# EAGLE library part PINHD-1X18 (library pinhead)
PIN HEADER
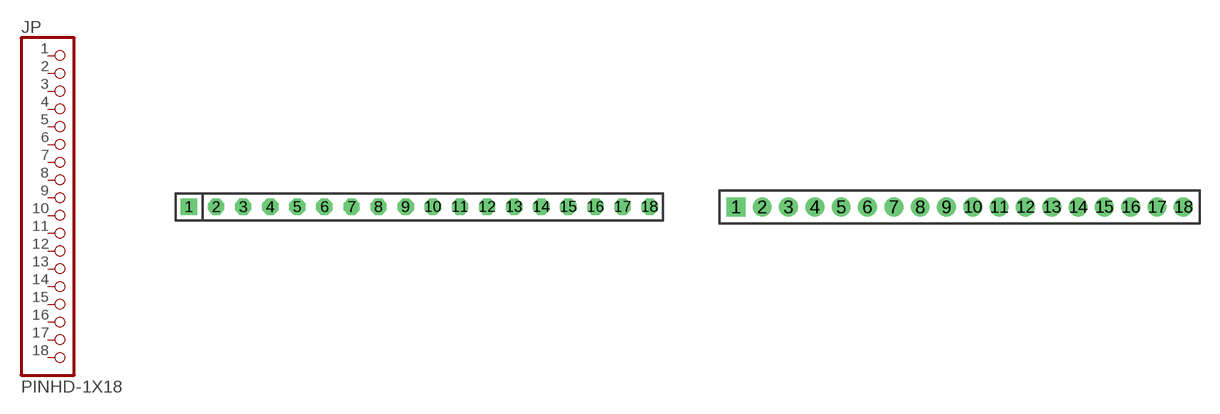
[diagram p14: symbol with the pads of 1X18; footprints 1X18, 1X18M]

Designator prefix JP

## PINHD-1X18  [1X18]
1  1  pas
2  2  pas
3  3  pas
4  4  pas
5  5  pas
6  6  pas
7  7  pas
8  8  pas
9  9  pas
10  10  pas
11  11  pas
12  12  pas
13  13  pas
14  14  pas
15  15  pas
16  16  pas
17  17  pas
18  18  pas

## PINHD-1X18M  [1X18M]
Pads as for 1X18

## Footprint 1X18 (pad centres in mm)
PIN HEADER - 0.1"
drill 1.016 square: 1 -21.59,0
drill 1.016 octagon: 2 -19.05,0; 3 -16.51,0; 4 -13.97,0; 5 -11.43,0; 6 -8.89,0; 7 -6.35,0; 8 -3.81,0; 9 -1.27,0; 10 1.27,0; 11 3.81,0; 12 6.35,0; 13 8.89,0; 14 11.43,0; 15 13.97,0; 16 16.51,0; 17 19.05,0; 18 21.59,0

## Footprint 1X18M (pad centres in mm)
PIN HEADER - 2MM"
drill 0.914 square: 1 -17,0
drill 0.914 round: 2 -15,0; 3 -13,0; 4 -11,0; 5 -9,0; 6 -7,0; 7 -5,0; 8 -3,0; 9 -1,0; 10 1,0; 11 3,0; 12 5,0; 13 7,0; 14 9,0; 15 11,0; 16 13,0; 17 15,0; 18 17,0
